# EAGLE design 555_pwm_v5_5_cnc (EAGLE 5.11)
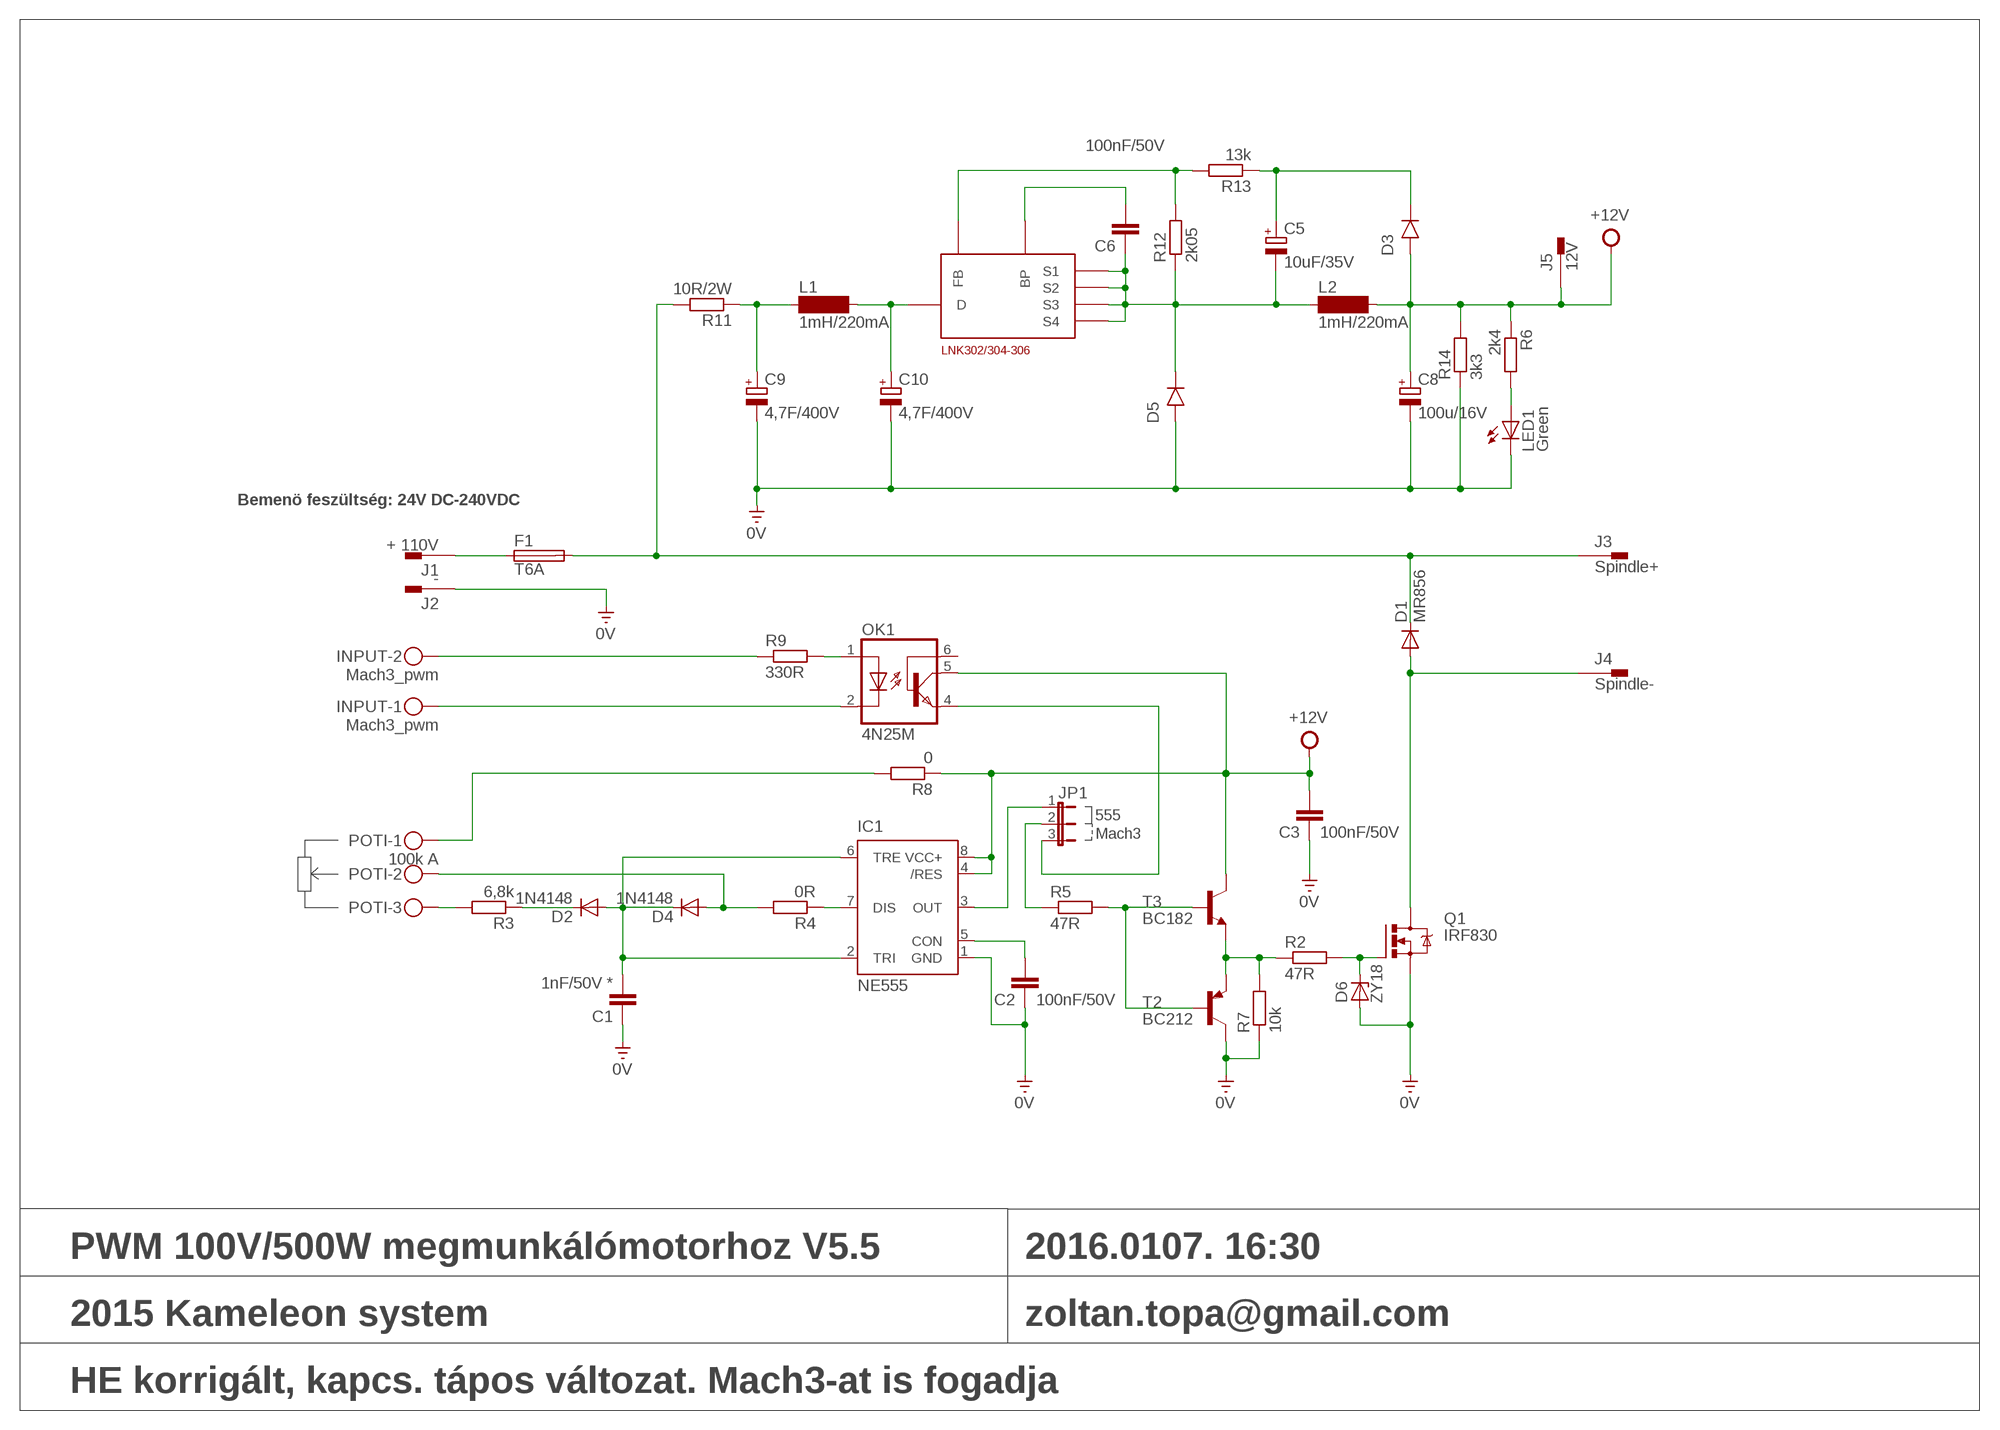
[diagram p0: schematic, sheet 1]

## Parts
C1  1nF/50V *  C-EU025_050-055X075  [C025_050-055X075]
C2  100nF/50V  C-EU025_050-055X075  [C025_050-055X075]
C3  100nF/50V  C-EU025_050-055X075  [C025_050-055X075]
C5  10uF/35V  CPOL-EUE2.5-5  [E2,5-5]
C6  100nF/50V  C-EU025_050-055X075  [C025_050-055X075]
C8  100u/16V  CPOL-EUE2.5-7  [E2,5-7]
C9  4,7F/400V  CPOL-EUE2.5-7  [E2,5-7]
C10  4,7F/400V  CPOL-EUE2.5-7  [E2,5-7]
D1  MR856  1N5400  [DO201-15]
D2  1N4148  1N4148DO35-10  [DO35-10]
D3  1N4007  1N4001  [DO41-10]
D4  1N4148  1N4148DO35-10  [DO35-10]
D5  1N4007  1N4001  [DO41-10]
D6  ZY18  ZENER-DIODEDO35Z10  [DO35Z10]
F1  T6A  SH22,5A  [SH22,5A]
IC1  NE555  [DIL-08]
INPUT  Mach3_pwm  MKDSN1,5/2-5,08  [MKDSN1,5/2-5,08]
J1  + 110V  PIN2F061.100  [F061.100]
J2  -  PIN2F061.100  [F061.100]
J3  Spindle+  PIN2F061.100  [F061.100]
J4  Spindle-  PIN2F061.100  [F061.100]
J5  12V  PIN2F061.100  [F061.100]
JP1  JP2E  [JP2]
L1  1mH/220mA  BS11  [BS11]
L2  1mH/220mA  BS11  [BS11]
LED1  Green  LED5MM  [LED5MM]
LNK304PN  LNK304PN  LNK302/304-306DIL_08  [DIL08_LNK]
OK1  4N25M  [DIL06]
POTI  100k A  MKDSN1,5/3-5,08  [MKDSN1,5/3-5,08]
Q1  IRF830  IRF540  [TO220BV]
R2  47R  R-EU_0309/10  [0309/10]
R3  6,8k  R-EU_0309/10  [0309/10]
R4  0R  R-EU_0309/10  [0309/10]
R5  47R  R-EU_0309/10  [0309/10]
R6  2k4  R-EU_0309/10  [0309/10]
R7  10k  R-EU_0309/10  [0309/10]
R8  0  R-EU_0309/10  [0309/10]
R9  330R  R-EU_0309/10  [0309/10]
R11  10R/2W  R-EU_0617/22  [0617/22]
R12  2k05  R-EU_0309/10  [0309/10]
R13  13k  R-EU_0309/10  [0309/10]
R14  3k3  R-EU_0309/10  [0309/10]
T2  BC212  -PNP-TO92-CBE  [TO92-CBE]
T3  BC182  2N4124-NPN-TO92-CBE  [TO92-CBE]

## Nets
0V [power]: C1.1 C2.1 C3.1 C8.- C9.- C10.- D5.A(ANODE) D6.A IC1.1(GND) J2.A1 LED1.K(C) Q1.S R7.1 R14.1 T2.C
+12V: C3.2 C8.+ D3.A(ANODE) IC1.4(/RES) IC1.8(VCC+) J5.A1 L2.2 OK1.5(COL) R6.1 R8.1 R14.2 T3.C
N$2: D6.C Q1.G R2.2
N$3: C9.+ L1.1 R11.1
N$4: D1.A J4.A1 Q1.D
N$5 [power]: D1.C F1.2 J3.A1 R11.2
N$6: C10.+ L1.2 LNK304PN.D
N$8: R2.1 R7.2 T2.E T3.E
N$9: R5.2 T2.B T3.B
N$10: JP1.2 R5.1
N$11: C1.2 D2.A D4.C IC1.2(TRI) IC1.6(TRE)
N$12: D2.C R3.1
N$13: POTI.1 R8.2
N$14: D4.A POTI.2 R4.2
N$15: C2.2 IC1.5(CON)
N$16: IC1.3(OUT) JP1.1
N$17: OK1.1(A) R9.2
N$18: INPUT.2 R9.1
N$19: INPUT.1 OK1.2(C)
N$20: JP1.3 OK1.4(EMI)
N$21: POTI.3 R3.2
N$22: C6.2 LNK304PN.BP
N$23: C5.- C6.1 D5.C(CATHODE) L2.1 LNK304PN.S1 LNK304PN.S2 LNK304PN.S3 LNK304PN.S4 R12.1
N$24: LNK304PN.FB R12.2 R13.2
N$25: C5.+ D3.C(CATHODE) R13.1
N$26: LED1.A R6.2
N$27 [power]: F1.1 J1.A1
N$28: IC1.7(DIS) R4.1
Unconnected: J1.A2(1.1) J2.A2(1.1) J3.A2(1.1) J4.A2(1.1) J5.A2(1.1) OK1.6(BAS)

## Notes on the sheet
- Bemenö feszültség: 24V DC-240VDC
- 555
- Mach3
- PWM 100V/500W megmunkálómotorhoz V5.5 | 2016.0107. 16:30
- 2015 Kameleon system | zoltan.topa@gmail.com
- HE korrigált, kapcs. tápos változat. Mach3-at is fogadja

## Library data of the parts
C1-C3 C6 = Kameleon_2013:C-EU: CAPACITOR, European symbol
C5 C8-C10 = rcl:CPOL-EU: POLARIZED CAPACITOR, European symbol
D1 = diode:1N5400: DIODE
D2 D4 = diode:1N4148: DIODE
D3 D5 = tango:1N4001: DIODE
D6 = diode:ZENER-DIODE: Z-Diode
F1 = fuse:SH22,5A: FUSE HOLDER; MPN: 0031.7701.11; OC_FARNELL: unknown; OC_NEWARK: 04F1224
IC1 = st-microelectronics-2:NE555: General purpose bipolar Timer
INPUT = con-phoenix-508:MKDSN1,5/2-5,08: MKDSN 1,5/ 2-5,08 Printklemme; MPN: MKDSN 1,5/2-5.08; OC_FARNELL: 1792903; OC_NEWARK: 30M2397
J1-J5 = con-faston:PIN2: Flachstecker Typ Tyco/Electronics/AMP TAB, FASTON; OC_FARNELL: unknown; OC_NEWARK: unknown
JP1 = jumper:JP2E: JUMPER
L1 L2 = inductor-neosid:BS: INDUCTOR; OC_FARNELL: unknown; OC_NEWARK: unknown
LED1 = Kameleon_2013:LED: LED
LNK304PN = linkswitch:LNK302/304-306
OK1 = optocoupler:4N*?M: General Purpose 6-Pin Phototransistor Optocouplers Source: http://www.fairchildsemi.com/ds/4N/4N35-M.pdf; MPN: 4N25-M; OC_FARNELL: 1021349; OC_NEWARK: 98K9084
POTI = con-phoenix-508:MKDSN1,5/3-5,08: MKDSN 1,5/ 3-5,08 Printklemme Nennstrom: 13,5 A Nennspannung: 250 V Rastermaß: 5,08 mm Polzahl: 3 Anschlussart: Schraubanschluss Montage: Löten Anschlussrichtung Leiter/Platine: 0 ° Artikelnummer: 1729131 Source: http://eshop.phoenixcontact.com .. 1729131.pdf; MPN: SMKDSN1,5/3-5,08; OC_FARNELL: 1792904; OC_NEWARK: 70R0299
Q1 = transistor-power:IRF540: HEXFET Power MOSFET
R2-R9 R11-R14 = resistor:R-EU_: RESISTOR, European symbol
T2 = transistor-neu-to92:*-PNP-: PNP Transistror
T3 = transistor:*-NPN-: NPN Transistror BF959 corrected 2008.03.06

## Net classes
0 default: width 0.635 mm, drill 0.8 mm
1 power: width 2.032 mm

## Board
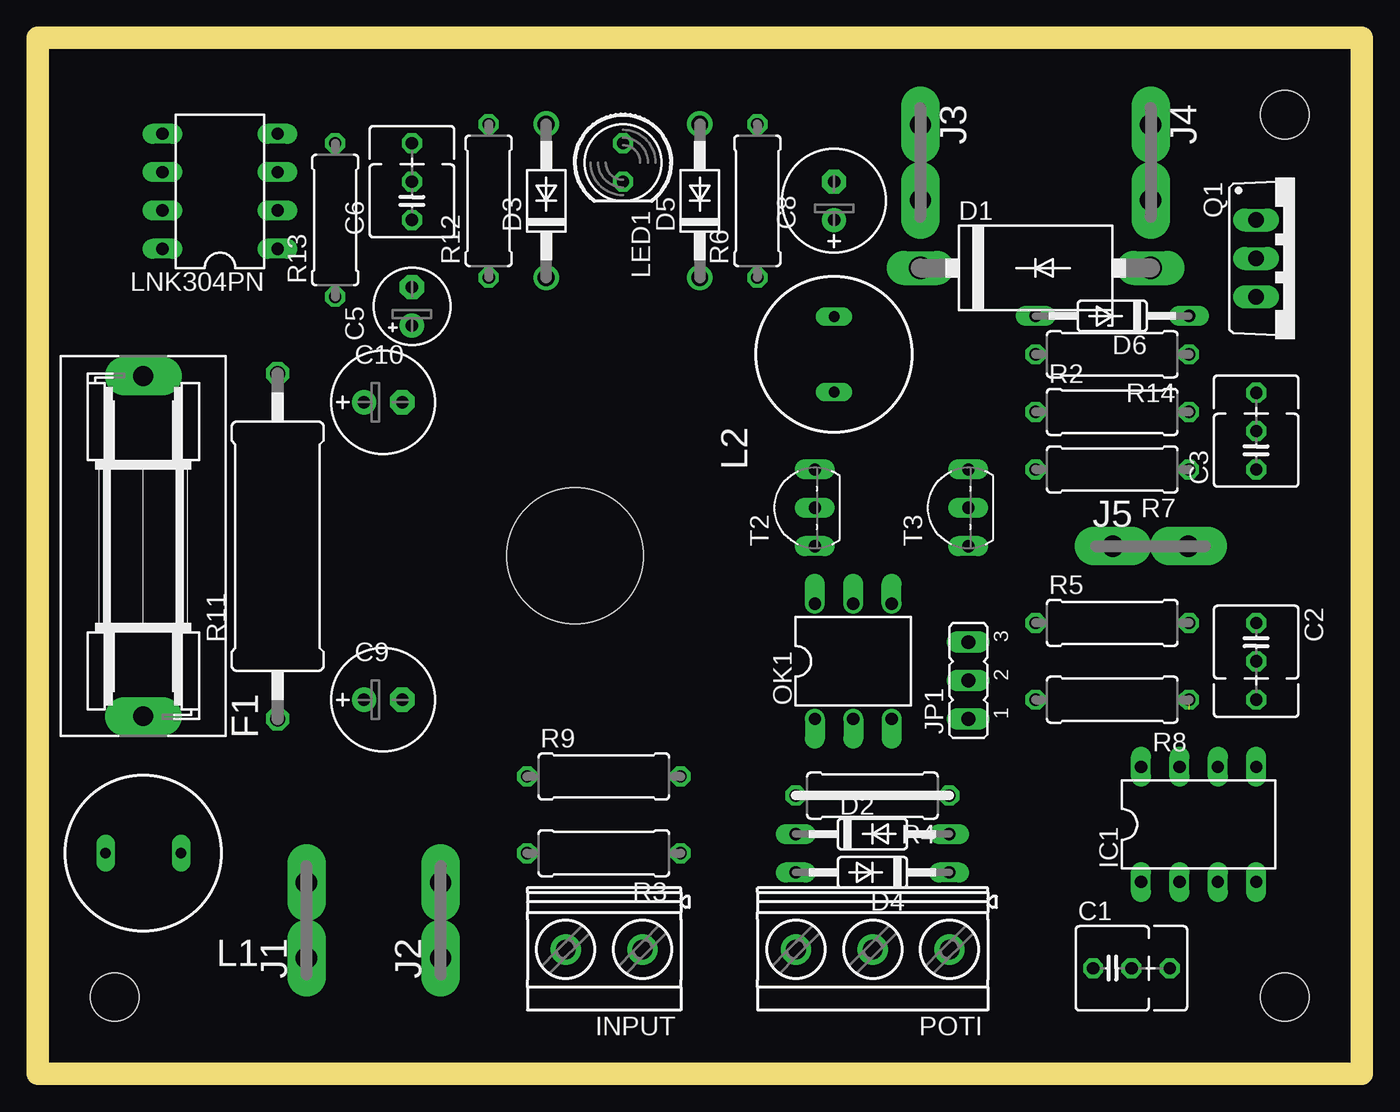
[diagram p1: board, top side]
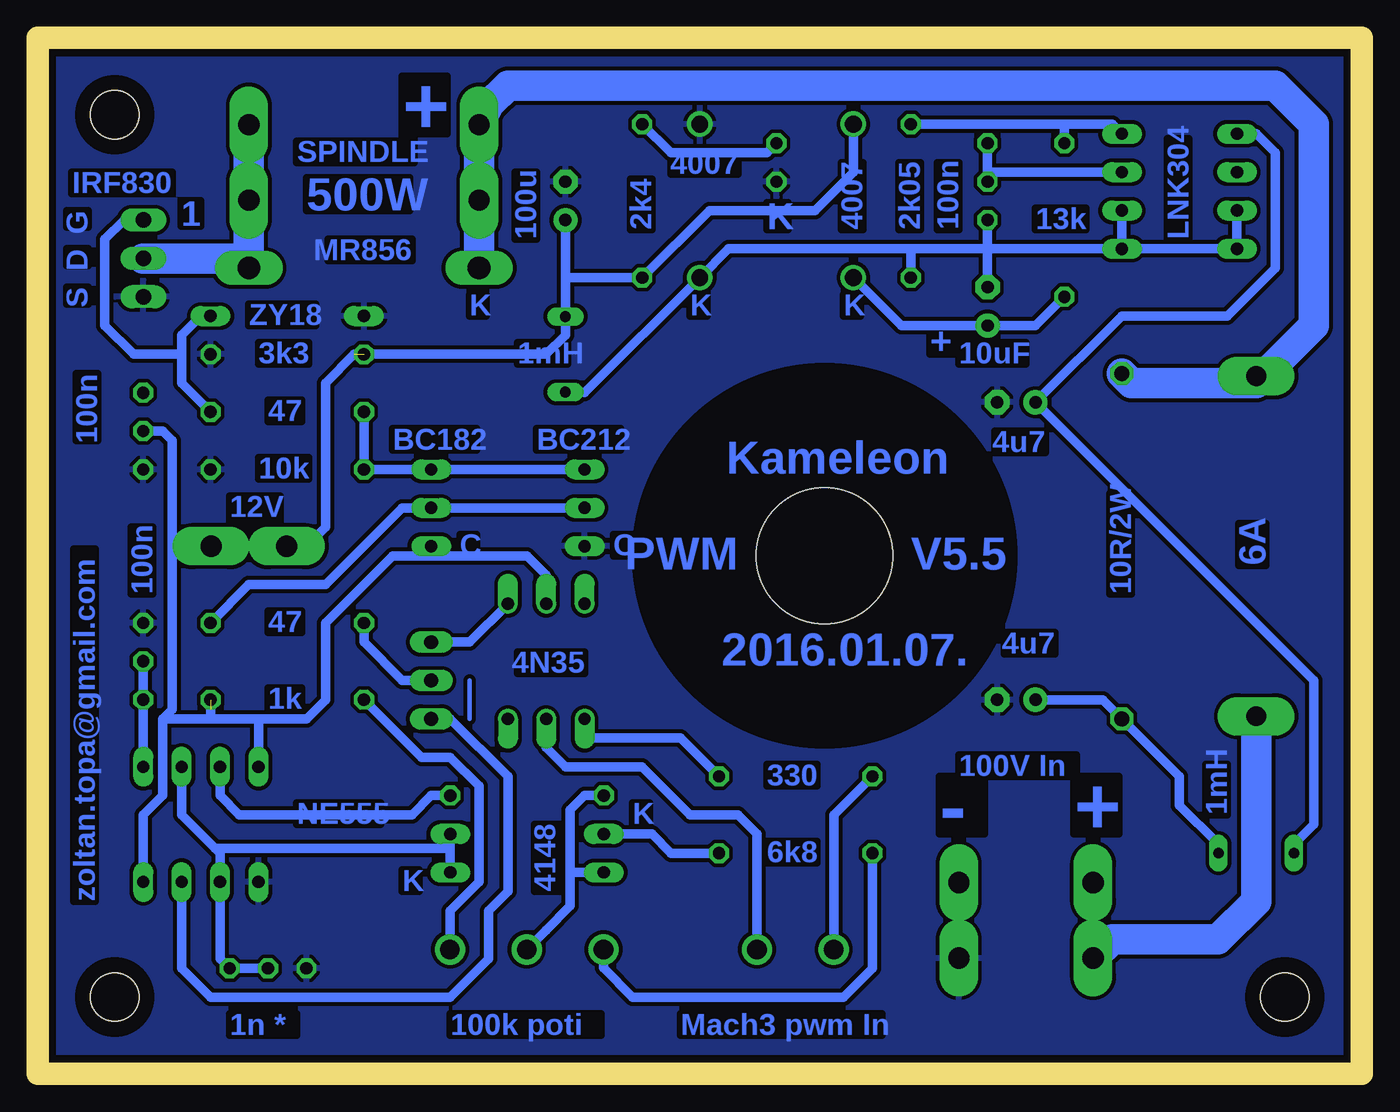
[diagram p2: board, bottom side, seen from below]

Size 87.63 x 68.58 mm. Coordinates in mm from the lower left corner, seen from the top.
Outline: 0,0 87.63,0 87.63,68.58 0,68.58 0,0
Copper layers (1*16): Top 0.035mm / dielectric 1.5mm / Bottom 0.035mm
Design rules "default": minimum track width 10mil, minimum drill 24mil, track to track 8mil, track to pad 8mil, pad to pad 8mil, via to via 8mil, smd to smd 8mil, copper to edge 40mil, drill to drill 8mil, minimum pad ring 10mil, minimum via ring 8mil, stop-mask expansion 4mil, vias tented up to drill 0mil, thermal gap 10mil
Holes 9 mm at 35.56,34.29
Holes 3.2 mm at 82.55,5.08 5.08,5.08 82.55,63.5
bRestrict: area 29.6,28.3 to 41.6,40.3
Milling: 4 lines

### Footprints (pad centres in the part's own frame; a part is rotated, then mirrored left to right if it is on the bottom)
C025_050-055X075 = drill 0.813 octagon: 1 -1.27,0; 2 1.27,0; 3 3.81,0
E2,5-5 = drill 0.813 pad 1.6 round: + -1.27,0 | drill 0.813 pad 1.6 octagon: - 1.27,0
E2,5-7 = drill 0.813 pad 1.6 round: + -1.27,0 | drill 0.813 pad 1.6 octagon: - 1.27,0
DO201-15 = drill 1.499 long: A 7.62,0; C -7.62,0
DO35-10 = drill 0.813 long: A 5.08,0; C -5.08,0
DO41-10 = drill 1.118 round: A 5.08,0; C -5.08,0
DO35Z10 = drill 0.813 long: A 5.08,0; C -5.08,0
SH22,5A = drill 1.321 pad 2.54 long: 1 -11.252,0; 2 11.252,0
DIL-08 = drill 0.813 long: 1 -3.81,-3.81; 2 -1.27,-3.81; 3 1.27,-3.81; 4 3.81,-3.81; 5 3.81,3.81; 6 1.27,3.81; 7 -1.27,3.81; 8 -3.81,3.81
MKDSN1,5/2-5,08 = drill 1.3 pad 2 round: 1 -2.561,0.025; 2 2.519,0.025
F061.100 = drill 1.4 pad 2.54 long: A1 -2.5,0; A2 2.5,0
JP2 = drill 0.914 long: 1 -2.54,0; 2 0,0; 3 2.54,0
BS11 = drill 0.7 long: 1 -2.5,0; 2 2.5,0
LED5MM = drill 0.813 octagon: A -1.27,0; K 1.27,0
DIL08_LNK = drill 0.813 long: BP 1.27,-3.81; D 3.81,3.81; FB 3.81,-3.81; N/C 1.27,3.81; S1 -3.81,-3.81; S2 -1.27,-3.81; S3 -1.27,3.81; S4 -3.81,3.81
DIL06 = drill 0.813 offset: 1 -2.54,-3.81; 2 0,-3.81; 3 2.54,-3.81; 4 2.54,3.81; 5 0,3.81; 6 -2.54,3.81
MKDSN1,5/3-5,08 = drill 1.3 pad 2 round: 1 -7.641,0.025; 2 -2.561,0.025; 3 2.519,0.025
TO220BV = drill 1.016 long: D 0,-2.54; G -2.54,-2.54; S 2.54,-2.54
0309/10 = drill 0.813 octagon: 1 -5.08,0; 2 5.08,0
0617/22 = drill 1.016 octagon: 1 -11.43,0; 2 11.43,0
TO92-CBE = drill 0.813 long: B 0,0; C -2.54,0; E 2.54,0

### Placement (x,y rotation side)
C1  71.12,6.99 0 top
C2  80.64,28.57 270 top
C3  80.64,41.27 90 top
C5  24.77,50.8 90 top
C6  24.77,57.78 90 top
C8  52.7,57.78 90 top
C9  22.86,24.77 0 top
C10  22.86,44.45 0 top
D1  66.04,53.34 0 top
D2  55.24,15.88 0 top
D3  33.66,57.78 90 top
D4  55.24,13.34 180 top
D5  43.81,57.78 90 top
D6  71.12,50.16 180 top
F1  6.99,34.92 90 top
IC1  76.83,16.51 0 top
INPUT  37.47,8.26 180 top
J1  17.78,10.16 90 top
J2  26.67,10.16 90 top
J3  58.42,60.33 270 top
J4  73.66,60.33 270 top
J5  73.66,34.92 0 top
JP1  61.59,26.04 90 top
L1  6.99,14.61 180 top
L2  52.7,47.62 90 top
LED1  38.73,60.33 270 top
LNK304PN  12.06,58.42 90 top
OK1  53.98,27.3 0 top
POTI  52.7,8.26 180 top
Q1  83.19,53.98 270 top
R2  71.12,43.81 0 top
R3  37.47,14.61 180 top
R4  55.24,18.41 180 top
R5  71.12,29.84 0 top
R6  47.62,57.78 90 top
R7  71.12,40.01 180 top
R8  71.12,24.77 180 top
R9  37.47,19.68 0 top
R11  15.88,34.92 90 top
R12  29.84,57.78 90 top
R13  19.68,56.52 90 top
R14  71.12,47.62 180 top
T2  51.44,37.47 90 top
T3  61.59,37.47 90 top

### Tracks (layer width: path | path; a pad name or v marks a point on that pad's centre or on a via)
0V
  pour Bottom (isolate 0.254): -0.64,-0.64 88.27,-0.64 88.27,69.22 -0.64,69.22
+12V  (2 unrouted)
  Bottom 0.635: OK1.5 53.98,33.02 55.24,34.29 61.59,34.29 | IC1.4 80.64,17.14 79.38,18.41 79.38,23.5 | 61.59,34.29 T3.C | 61.59,34.29 64.14,34.29 68.58,29.84 68.58,24.77 69.85,23.5 73.03,23.5 | 52.7,52.7 L2.2 52.7,48.9 53.98,47.62 66.67,47.62 68.58,45.72 68.58,36.2 69.85,34.92 J5.A1 78.74,34.92 | 52.7,52.7 C8.+ | 73.03,23.5 76.2,23.5 | 76.2,23.5 79.38,23.5 | 79.38,23.5 78.74,24.13 78.74,34.92 | 76.2,23.5 76.2,24.13 | 73.03,23.5 IC1.8 | 78.74,34.92 78.74,41.91 79.38,42.55 C3.2 | D3.A 33.66,59.69 36.2,57.15 43.18,57.15 R6.1 52.7,52.7
N$1
  Bottom 0.305: 59.05,23.5 59.05,26.04
N$2
  Bottom 0.635: Q1.G 81.92,56.52 83.19,55.24 83.19,49.53 81.28,47.62 78.11,47.62 | R2.2 78.11,45.72 78.11,47.62 | 78.11,47.62 78.11,48.9 76.83,50.16 D6.C
N$3
  Bottom 0.635: C9.+ 17.14,24.77 R11.1 12.06,19.68 12.06,17.78 9.53,15.24 L1.1
N$4
  Bottom 2.032: Q1.D 74.3,53.98 D1.A J4.A1
N$5
  Bottom 2.032: J3.A1 57.78,64.14 56.52,65.41 5.71,65.41 3.17,62.87 3.17,49.53 6.99,45.72 | J3.A1 58.42,62.87 | 6.99,45.72 15.24,45.72 R11.2 | F1.2 7.8,46.35 6.99,45.72 | J3.A1 D1.C
N$6
  Bottom 0.635: LNK304PN.D 6.99,62.23 5.71,60.96 5.71,53.34 8.89,50.16 15.88,50.16 C10.+ 3.17,26.04 3.17,16.51 4.49,15.2 L1.2
N$8
  Bottom 0.635: T2.E T3.E R7.2 R2.1
N$9
  Bottom 0.635: T2.B T3.B 63.5,37.47 68.58,32.38 73.66,32.38 R5.2
N$10
  Bottom 0.635: JP1.2 63.5,26.04 66.04,28.57 R5.1
N$11
  Bottom 0.635: IC1.6 78.11,17.14 75.88,14.92 | 75.88,14.92 75.56,14.61 IC1.2 75.56,7.62 74.93,6.99 C1.2 | 60.33,15.24 D2.A | D4.C 60.33,15.24 | 60.33,15.24 60.64,14.92 75.88,14.92
N$12
  Bottom 0.635: R3.1 45.72,14.61 46.99,15.88 D2.C
N$13
  Bottom 0.635: POTI.1 60.35,10.77 58.42,12.7 58.42,19.05 60.33,20.95 62.23,20.95 R8.2
N$14
  Bottom 0.635: POTI.2 54,9.5 52.39,11.11 52.39,13.34 | R4.2 51.44,18.41 52.39,17.46 52.39,13.34 | D4.A 52.39,13.34
N$15
  Bottom 0.635: IC1.5 C2.2
N$16
  Bottom 0.635: JP1.1 60.33,23.5 56.52,19.68 56.52,12.06 57.78,10.79 57.78,7.62 60.33,5.08 76.2,5.08 78.11,6.99 IC1.3
N$17
  Bottom 0.635: R9.2 45.09,22.23 51.44,22.23 OK1.1
N$18
  Bottom 0.635: R9.1 34.95,17.12 INPUT.2
N$19
  Bottom 0.635: OK1.2 53.98,21.59 52.7,20.32 47.62,20.32 44.45,17.14 41.27,17.14 40.03,15.9 INPUT.1
N$20
  Bottom 0.635: JP1.3 59.05,28.57 OK1.4
N$21
  Bottom 0.635: R3.2 32.38,6.99 34.29,5.08 48.26,5.08 50.19,7.01 POTI.3
N$22
  Bottom 0.635: 24.77,59.69 24.77,61.59 | LNK304PN.BP 24.77,59.69 | 24.77,59.69 C6.2
N$23
  Bottom 0.635: LNK304PN.S3 LNK304PN.S4 LNK304PN.S1 | LNK304PN.S1 LNK304PN.S2 | L2.1 51.44,45.09 D5.C 41.91,54.61 29.84,54.61 | 24.77,54.61 C5.- | 24.77,54.61 C6.1 | 29.84,54.61 R12.1 | 24.77,54.61 29.84,54.61 | LNK304PN.S1 24.77,54.61
N$24
  Bottom 0.635: 19.68,62.87 R12.2 | LNK304PN.FB 16.51,62.87 19.68,62.87 | 19.68,62.87 R13.2
N$25
  Bottom 0.635: R13.1 21.59,49.53 C5.+ 30.48,49.53 D3.C
N$26
  Bottom 0.635: LED1.A 39.37,60.96 45.72,60.96 R6.2
N$27
  Bottom 2.032: J1.A1 16.51,8.89 9.53,8.89 6.99,11.43 F1.1
N$28
  Bottom 0.635: R4.1 61.59,18.41 62.87,17.14 74.3,17.14 75.56,18.41 IC1.7

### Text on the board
Bottom: + | 4007 | SPINDLE | IRF830 | 1 | 500W | G | 13k | 100n | 2k05 | 4007 | K | 2k4 | LNK304 | 100u | MR856 | D | S | K | K | K | ZY18 | + | 10uF | 1mH | 3k3 | 100n | 4u7 | 47 | Kameleon | BC212 | BC182 | 10k | 12V | V5.5 | PWM | 6A | C | C | 10R/2W | 100n | 4u7 | 2016.01.07. | 47 | 4N35 | 1k | 100V In | 330 | 1mH | K | NE555 | + | - | 6k8 | 4148 | K | zoltan.topa@gmail.com | Mach3 pwm In | 100k poti | 1n *
tValues: K | G D S | 1 | K | K | K | K | K | K
bStop: + | 4007 | SPINDLE | IRF830 | 1 | 500W | G | 13k | 100n | 2k05 | 4007 | K | 2k4 | LNK304 | 100u | MR856 | D | S | K | K | K | ZY18 | + | 10uF | 1mH | 3k3 | 100n | 4u7 | 47 | Kameleon | BC212 | BC182 | 10k | 12V | V5.4 | PWM | 6A | C | C | 10R/2W | 100n | 4u7 | 2016.01.07. | 47 | 4N35 | 1k | 100V In | 330 | 1mH | K | NE555 | + | - | 6k8 | 4148 | K | zoltan.topa@gmail.com | Mach3 pwm In | 100k poti | 1n *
